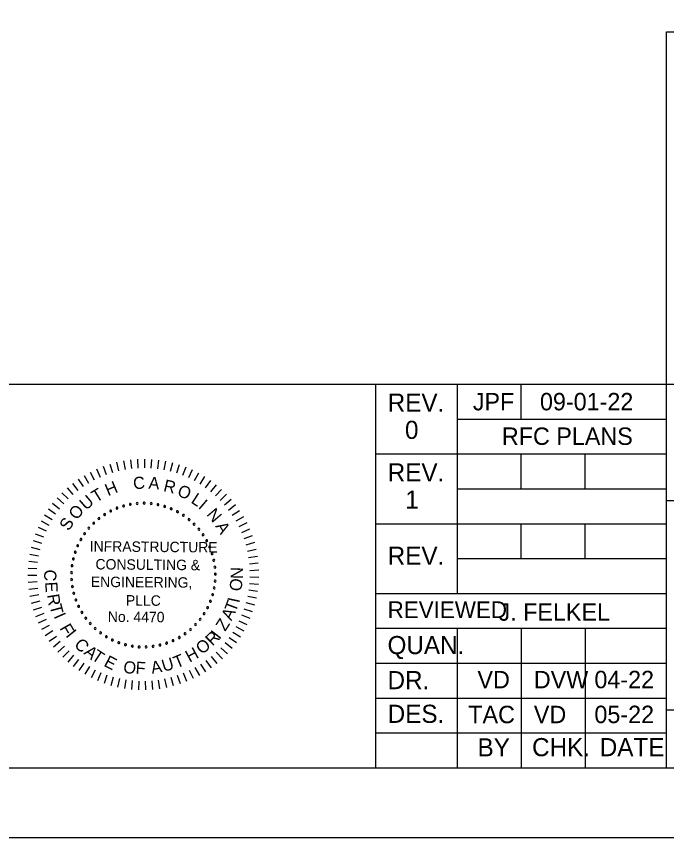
# Model space of a CAD drawing. Extents: x 96 to 240, y 601 to 689.
# Drawn here: x 197.53 to 216.17, y 601 to 624.55 of the extents above; entities that cross this region are included whole.
import ezdxf

# ---------------------------------------------------------------- set-up
doc = ezdxf.new("R2010")
doc.units = 0
for name, color, linetype in [('BR_BORDER LINES', 7, 'Continuous'), ('BR_TEXT', 7, 'Continuous'), ('Level 31', 7, 'Continuous')]:
    doc.layers.add(name, color=color, linetype=linetype)

msp = doc.modelspace()

# ---------------------------------------------------------------- linework, layer by layer
at = {"layer": 'BR_BORDER LINES'}
for p, q in [((216.17, 603.003), (216.17, 624.11)), ((216.17, 624.11), (237.837, 624.11)), ((186.375, 614.004), (207.836, 614.004)), ((207.836, 603.003), (207.836, 614.004)), ((207.836, 614.004), (237.837, 614.004)), ((210.169, 614.004), (210.169, 608.004)), ((212.003, 613.004), (212.003, 614.004)), ((210.169, 613.004), (216.17, 613.004)), ((207.836, 612.004), (216.17, 612.004)), ((212.003, 611.004), (212.003, 612.004)), ((213.836, 611.004), (213.836, 612.004)), ((210.169, 611.004), (216.17, 611.004)), ((216.17, 610.67), (216.17, 610.67)), ((216.17, 610.67), (237.838, 610.67)), ((207.836, 610.004), (216.17, 610.004)), ((212.003, 609.004), (212.003, 610.004)), ((213.836, 609.004), (213.836, 610.004)), ((210.169, 609.004), (216.17, 609.004)), ((207.836, 608.004), (216.17, 608.004)), ((207.836, 607.004), (216.17, 607.004)), ((210.169, 607.004), (210.169, 603.003)), ((212.003, 607.004), (212.003, 603.003)), ((213.836, 607.004), (213.836, 603.003)), ((207.836, 606.004), (216.17, 606.004)), ((207.836, 605.004), (216.17, 605.004)), ((216.17, 604.67), (237.837, 604.67)), ((207.836, 604.003), (216.17, 604.003)), ((103.173, 603.003), (237.837, 603.003))]:
    msp.add_line(p, q, dxfattribs=at)
at = {"layer": 'BR_TEXT'}
for p, q in [((200.401, 611.767), (200.46, 611.519)), ((200.599, 611.808), (200.643, 611.557)), ((200.798, 611.836), (200.827, 611.583)), ((201, 611.853), (201.013, 611.599)), ((201.202, 611.857), (201.199, 611.602)), ((201.403, 611.849), (201.386, 611.595)), ((201.604, 611.829), (201.571, 611.576)), ((201.804, 611.796), (201.755, 611.546)), ((202, 611.752), (201.937, 611.505)), ((199.646, 611.485), (199.763, 611.259)), ((199.828, 611.573), (199.931, 611.34)), ((200.015, 611.649), (200.104, 611.411)), ((200.206, 611.714), (200.28, 611.47)), ((202.194, 611.695), (202.116, 611.453)), ((202.384, 611.627), (202.291, 611.39)), ((202.57, 611.547), (202.463, 611.316)), ((199.299, 611.278), (199.443, 611.068)), ((199.469, 611.387), (199.6, 611.169)), ((202.75, 611.456), (202.629, 611.232)), ((202.925, 611.354), (202.79, 611.138)), ((198.981, 611.03), (199.149, 610.839)), ((199.136, 611.159), (199.293, 610.958)), ((203.093, 611.242), (202.945, 611.035)), ((203.253, 611.12), (203.093, 610.922)), ((198.833, 610.892), (199.013, 610.712)), ((203.406, 610.988), (203.235, 610.8)), ((203.551, 610.847), (203.368, 610.67)), ((198.565, 610.59), (198.766, 610.433)), ((198.695, 610.745), (198.885, 610.576)), ((203.687, 610.698), (203.493, 610.532)), ((203.813, 610.54), (203.61, 610.387)), ((198.446, 610.428), (198.655, 610.283)), ((203.93, 610.376), (203.718, 610.235)), ((198.237, 610.082), (198.463, 609.964)), ((198.336, 610.258), (198.554, 610.127)), ((204.036, 610.204), (203.816, 610.076)), ((198.149, 609.9), (198.381, 609.796)), ((204.132, 610.026), (203.904, 609.912)), ((204.217, 609.843), (203.982, 609.743)), ((198.072, 609.714), (198.31, 609.624)), ((204.29, 609.655), (204.05, 609.569)), ((198.007, 609.522), (198.25, 609.448)), ((204.352, 609.462), (204.107, 609.392)), ((197.911, 609.13), (198.162, 609.086)), ((197.953, 609.328), (198.2, 609.268)), ((204.402, 609.267), (204.153, 609.211)), ((197.882, 608.93), (198.135, 608.901)), ((204.44, 609.068), (204.188, 609.028)), ((197.864, 608.729), (198.119, 608.716)), ((204.465, 608.868), (204.212, 608.843)), ((204.479, 608.667), (204.224, 608.657)), ((197.859, 608.527), (198.114, 608.529)), ((204.48, 608.465), (204.225, 608.471)), ((197.867, 608.326), (198.121, 608.343)), ((204.469, 608.263), (204.215, 608.284)), ((197.886, 608.125), (198.139, 608.157)), ((197.918, 607.925), (198.168, 607.973)), ((204.445, 608.062), (204.193, 608.099)), ((197.962, 607.728), (198.209, 607.791)), ((204.362, 607.667), (204.117, 607.735)), ((204.41, 607.864), (204.161, 607.916)), ((198.018, 607.534), (198.26, 607.612)), ((204.303, 607.474), (204.062, 607.557)), ((198.086, 607.344), (198.323, 607.437)), ((198.165, 607.158), (198.396, 607.265)), ((204.231, 607.285), (203.996, 607.382)), ((198.255, 606.977), (198.479, 607.098)), ((204.055, 606.922), (203.833, 607.047)), ((204.149, 607.101), (203.92, 607.212)), ((198.356, 606.802), (198.572, 606.937)), ((198.468, 606.634), (198.675, 606.782)), ((203.951, 606.749), (203.737, 606.887)), ((198.589, 606.473), (198.787, 606.633)), ((203.712, 606.424), (203.516, 606.587)), ((203.836, 606.583), (203.631, 606.734)), ((198.72, 606.319), (198.909, 606.491)), ((198.861, 606.174), (199.038, 606.357)), ((203.434, 606.131), (203.26, 606.316)), ((203.577, 606.273), (203.392, 606.448)), ((199.01, 606.038), (199.176, 606.231)), ((199.167, 605.911), (199.32, 606.114)), ((203.124, 605.873), (202.973, 606.079)), ((203.283, 605.997), (203.12, 606.193)), ((199.331, 605.794), (199.472, 606.005)), ((199.502, 605.687), (199.63, 605.907)), ((202.784, 605.655), (202.659, 605.878)), ((202.957, 605.759), (202.819, 605.973)), ((199.68, 605.59), (199.794, 605.818)), ((199.863, 605.505), (199.963, 605.739)), ((200.051, 605.431), (200.136, 605.671)), ((200.243, 605.368), (200.314, 605.613)), ((202.037, 605.351), (201.97, 605.597)), ((202.231, 605.41), (202.149, 605.651)), ((202.42, 605.481), (202.323, 605.716)), ((202.604, 605.562), (202.494, 605.792)), ((200.438, 605.318), (200.494, 605.566)), ((200.636, 605.279), (200.677, 605.53)), ((200.836, 605.253), (200.862, 605.506)), ((201.038, 605.238), (201.048, 605.493)), ((201.24, 605.236), (201.234, 605.491)), ((201.441, 605.247), (201.42, 605.501)), ((201.642, 605.269), (201.606, 605.522)), ((201.841, 605.304), (201.789, 605.554))]:
    msp.add_line(p, q, dxfattribs=at)
for centre, start, end in [((200.601, 610.512), 16.1422, 196.1422), ((200.795, 610.558), 10.6038, 190.6038), ((200.795, 610.558), 190.6038, 10.6038), ((200.993, 610.585), 5.0653, 185.0653), ((200.993, 610.585), 185.0653, 5.0653), ((201.192, 610.593), 359.5268, 179.5268), ((201.192, 610.593), 179.5268, 359.5268), ((201.391, 610.581), 353.9884, 173.9884), ((201.391, 610.581), 173.9884, 353.9884), ((201.588, 610.55), 348.4499, 168.4499), ((201.588, 610.55), 168.4499, 348.4499), ((200.231, 610.366), 27.2191, 207.2191), ((200.231, 610.366), 207.2191, 27.2191), ((200.412, 610.448), 21.6807, 201.6807), ((200.412, 610.448), 201.6807, 21.6807), ((200.601, 610.512), 196.1422, 16.1422), ((201.781, 610.5), 162.9114, 342.9114), ((201.781, 610.5), 342.9114, 162.9114), ((201.968, 610.432), 157.373, 337.373), ((201.968, 610.432), 337.373, 157.373), ((202.148, 610.346), 151.8345, 331.8345), ((202.148, 610.346), 331.8345, 151.8345), ((199.896, 610.151), 38.2961, 218.2961), ((199.896, 610.151), 218.2961, 38.2961), ((200.058, 610.267), 32.7576, 212.7576), ((200.058, 610.267), 212.7576, 32.7576), ((202.319, 610.244), 146.2961, 326.2961), ((202.319, 610.244), 326.2961, 146.2961), ((202.479, 610.125), 140.7576, 320.7576), ((202.479, 610.125), 320.7576, 140.7576), ((199.608, 609.876), 49.373, 229.373), ((199.608, 609.876), 229.373, 49.373), ((199.745, 610.021), 43.8345, 223.8345), ((199.745, 610.021), 223.8345, 43.8345), ((202.627, 609.991), 135.2191, 315.2191), ((202.627, 609.991), 315.2191, 135.2191), ((202.761, 609.844), 129.6807, 309.6807), ((202.761, 609.844), 309.6807, 129.6807), ((199.485, 609.719), 54.9114, 234.9114), ((199.485, 609.719), 234.9114, 54.9114), ((202.88, 609.684), 124.1422, 304.1422), ((202.88, 609.684), 304.1422, 124.1422), ((199.288, 609.373), 65.9884, 245.9884), ((199.288, 609.373), 245.9884, 65.9884), ((199.378, 609.551), 60.4499, 240.4499), ((199.378, 609.551), 240.4499, 60.4499), ((202.984, 609.514), 118.6038, 298.6038), ((202.984, 609.514), 298.6038, 118.6038), ((203.07, 609.334), 113.0653, 293.0653), ((203.07, 609.334), 293.0653, 113.0653), ((199.216, 609.187), 71.5268, 251.5268), ((199.216, 609.187), 251.5268, 71.5268), ((203.139, 609.147), 107.5268, 287.5268), ((203.139, 609.147), 287.5268, 107.5268), ((199.161, 608.996), 77.0653, 257.0653), ((199.161, 608.996), 257.0653, 77.0653), ((203.189, 608.954), 101.9884, 281.9884), ((203.189, 608.954), 281.9884, 101.9884), ((199.126, 608.799), 82.6038, 262.6038), ((199.126, 608.799), 262.6038, 82.6038), ((203.221, 608.758), 96.4499, 276.4499), ((203.221, 608.758), 276.4499, 96.4499), ((199.109, 608.601), 88.1422, 268.1422), ((199.112, 608.402), 93.6807, 273.6807), ((199.109, 608.601), 268.1422, 88.1422), ((199.112, 608.402), 273.6807, 93.6807), ((203.233, 608.559), 90.9114, 270.9114), ((203.233, 608.559), 270.9114, 90.9114), ((199.134, 608.203), 99.2191, 279.2191), ((199.134, 608.203), 279.2191, 99.2191), ((203.2, 608.162), 79.8345, 259.8345), ((203.2, 608.162), 259.8345, 79.8345), ((203.226, 608.359), 85.373, 265.373), ((203.226, 608.359), 265.373, 85.373), ((199.175, 608.008), 104.7576, 284.7576), ((199.175, 608.008), 284.7576, 104.7576), ((203.155, 607.968), 74.2961, 254.2961), ((203.155, 607.968), 254.2961, 74.2961), ((199.235, 607.818), 110.2961, 290.2961), ((199.235, 607.818), 290.2961, 110.2961), ((203.092, 607.779), 68.7576, 248.7576), ((203.092, 607.779), 248.7576, 68.7576), ((199.312, 607.635), 115.8345, 295.8345), ((199.312, 607.635), 295.8345, 115.8345), ((199.407, 607.459), 121.373, 301.373), ((199.407, 607.459), 301.373, 121.373), ((203.01, 607.597), 63.2191, 243.2191), ((203.01, 607.597), 243.2191, 63.2191), ((199.519, 607.294), 126.9114, 306.9114), ((199.519, 607.294), 306.9114, 126.9114), ((202.797, 607.261), 52.1422, 232.1422), ((202.797, 607.261), 232.1422, 52.1422), ((202.912, 607.424), 57.6807, 237.6807), ((202.912, 607.424), 237.6807, 57.6807), ((199.646, 607.141), 132.4499, 312.4499), ((199.646, 607.141), 312.4499, 132.4499), ((199.787, 607), 137.9884, 317.9884), ((199.787, 607), 317.9884, 137.9884), ((202.667, 607.11), 46.6038, 226.6038), ((202.667, 607.11), 226.6038, 46.6038), ((199.941, 606.874), 143.5268, 323.5268), ((199.941, 606.874), 323.5268, 143.5268), ((200.107, 606.763), 149.0653, 329.0653), ((200.107, 606.763), 329.0653, 149.0653), ((202.366, 606.849), 35.5268, 215.5268), ((202.366, 606.849), 215.5268, 35.5268), ((202.523, 606.972), 41.0653, 221.0653), ((202.523, 606.972), 221.0653, 41.0653), ((200.282, 606.668), 154.6038, 334.6038), ((200.282, 606.668), 334.6038, 154.6038), ((200.466, 606.591), 160.1422, 340.1422), ((200.466, 606.591), 340.1422, 160.1422), ((200.657, 606.532), 345.6807, 165.6807), ((200.657, 606.532), 165.6807, 345.6807), ((201.644, 606.522), 13.373, 193.373), ((201.835, 606.577), 18.9114, 198.9114), ((201.835, 606.577), 198.9114, 18.9114), ((202.021, 606.65), 24.4499, 204.4499), ((202.021, 606.65), 204.4499, 24.4499), ((202.198, 606.741), 29.9884, 209.9884), ((202.198, 606.741), 209.9884, 29.9884), ((200.852, 606.492), 351.2191, 171.2191), ((200.852, 606.492), 171.2191, 351.2191), ((201.05, 606.471), 356.7576, 176.7576), ((201.05, 606.471), 176.7576, 356.7576), ((201.249, 606.469), 2.2961, 182.2961), ((201.249, 606.469), 182.2961, 2.2961), ((201.448, 606.486), 7.8345, 187.8345), ((201.448, 606.486), 187.8345, 7.8345), ((201.644, 606.522), 193.373, 13.373)]:
    msp.add_arc(centre, 0.028, start, end, dxfattribs=at)
at = {"layer": 'Level 31'}
msp.add_lwpolyline([(95.84, 601.004), (239.84, 601.004), (239.84, 689.004), (95.84, 689.004)], close=True, dxfattribs=at)

# ---------------------------------------------------------------- texts
at = {"layer": 'BR_TEXT'}
for s, height, p in [('REV.', 0.52, (208.175, 613.216)), ('JPF', 0.5, (210.615, 613.254)), ('09-01-22', 0.5, (212.54, 613.254)), ('0', 0.52, (208.67, 612.435)), ('RFC PLANS', 0.5, (211.449, 612.263)), ('REV.', 0.52, (208.175, 611.215)), ('1', 0.52, (208.678, 610.435)), ('REV.', 0.52, (208.175, 608.825)), ('REVIEWED', 0.48, (208.172, 607.298)), ('J. FELKEL', 0.5, (211.352, 607.221)), ('QUAN.', 0.52, (208.17, 606.264)), ('DR.', 0.52, (208.17, 605.258)), ('VD', 0.5, (210.748, 605.283)), ('DVW', 0.5, (212.365, 605.283)), ('04-22', 0.5, (214.101, 605.286)), ('DES.', 0.52, (208.175, 604.293)), ('TAC', 0.5, (210.485, 604.283)), ('VD', 0.5, (212.365, 604.283)), ('05-22', 0.5, (214.101, 604.286)), ('BY', 0.52, (210.751, 603.331)), ('CHK.', 0.52, (212.314, 603.337)), ('DATE', 0.52, (214.255, 603.337))]:
    msp.add_text(s, height=height, dxfattribs=at).set_placement(p)
for s, height, rotation, p in [('C', 0.349, 4.7281, (200.89, 610.987)), ('A', 0.349, 355.6981, (201.308, 611.007)), ('R', 0.349, 346.6681, (201.725, 610.939)), ('T', 0.349, 31.8182, (199.819, 610.599)), ('H', 0.349, 22.7882, (200.158, 610.789)), ('O', 0.349, 337.638, (202.116, 610.819)), ('U', 0.349, 40.8482, (199.526, 610.374)), ('L', 0.349, 327.108, (202.511, 610.618)), ('I', 0.349, 319.578, (202.721, 610.466)), ('O', 0.349, 49.8782, (199.258, 610.09)), ('N', 0.349, 310.548, (202.965, 610.263)), ('S', 0.349, 58.9083, (199.036, 609.777)), ('A', 0.349, 301.5179, (203.225, 609.934)), ('INFRASTRUCTURE', 0.29909, 359.5268, (199.631, 609.207)), ('CONSULTING &', 0.29909, 359.5268, (199.796, 608.693)), ('C', 0.349, 267.025, (198.336, 608.698)), ('N', 0.349, 89.2085, (204.022, 608.419)), ('ENGINEERING,', 0.29909, 359.5268, (199.662, 608.191)), ('O', 0.349, 83.2085, (203.978, 608.053)), ('E', 0.349, 273.025, (198.354, 608.331)), ('R', 0.349, 279.025, (198.405, 607.962)), ('PLLC', 0.2991, 359.5268, (200.668, 607.657)), ('T', 0.349, 285.025, (198.475, 607.647)), ('T', 0.349, 69.3954, (203.813, 607.446)), ('I', 0.349, 77.9093, (203.916, 607.716)), ('No. 4470', 0.2991, 359.5268, (200.15, 607.189)), ('A', 0.349, 63.3954, (203.69, 607.204)), ('I', 0.349, 293.7713, (198.593, 607.355)), ('Z', 0.349, 57.3954, (203.514, 606.899)), ('F', 0.349, 299.7713, (198.758, 607.01)), ('I', 0.349, 308.5268, (198.927, 606.795)), ('R', 0.349, 44.5268, (203.153, 606.479)), ('I', 0.349, 52.3339, (203.35, 606.668)), ('C', 0.349, 314.5268, (199.164, 606.515)), ('O', 0.349, 38.5268, (202.846, 606.239)), ('A', 0.349, 320.5268, (199.441, 606.28)), ('T', 0.349, 326.5268, (199.658, 606.126)), ('H', 0.349, 28.5268, (202.494, 606.015)), ('E', 0.349, 332.5268, (200.013, 605.935)), ('O', 0.349, 350.5268, (200.573, 605.74)), ('A', 0.349, 10.5268, (201.419, 605.697)), ('U', 0.349, 16.5268, (201.754, 605.751)), ('T', 0.349, 22.5268, (202.121, 605.848)), ('F', 0.349, 356.5268, (200.939, 605.703))]:
    msp.add_text(s, height=height, rotation=rotation, dxfattribs=at).set_placement(p)

doc.saveas('drawing.dxf')
